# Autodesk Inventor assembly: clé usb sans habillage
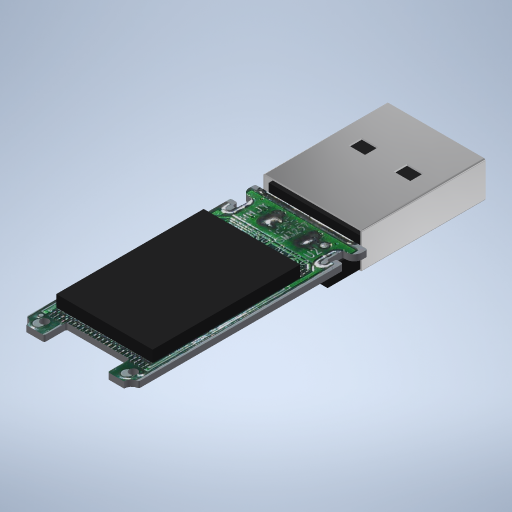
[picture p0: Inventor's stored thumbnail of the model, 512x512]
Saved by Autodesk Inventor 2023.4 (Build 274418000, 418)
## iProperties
Created: 2013-04
Part Number: clé usb sans habillage
Document SubType Name: Assembly
Designer: hilarion
Author: hilarion
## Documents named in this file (4)
- D:\travail\année 2025-2026\ITEC\it\clé usb sans habillage.iam
- D:\travail\année 2025-2026\ITEC\it\usb gris.ipt
- D:\travail\année 2025-2026\ITEC\it\usb noir.ipt
- D:\travail\année 2025-2026\ITEC\it\carte.ipt
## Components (3 placed, 3 different names)
1. usb gris:1 — Affleurement:1, Placage:1, Placage:2
2. usb noir:1 — Affleurement:1, Placage:1, Placage:2, Affleurement:2
3. carte:1 — Affleurement:2
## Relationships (4: Flush 2, Mate 2)
- Affleurement:1 [Flush]: usb gris:1 ↔ usb noir:1
- Placage:1 [Mate]: usb gris:1 ↔ usb noir:1
- Placage:2 [Mate]: usb gris:1 ↔ usb noir:1
- Affleurement:2 [Flush]: usb noir:1 ↔ carte:1
